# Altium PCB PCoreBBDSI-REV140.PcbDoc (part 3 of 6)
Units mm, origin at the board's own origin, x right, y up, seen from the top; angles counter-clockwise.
Board outline 100 x 72 mm, 6 copper layers (Top Layer, Int1 (GND), Int2 (Sign), Int3 (Sign), Int4 (GND), Bottom Layer), stack 1.551 mm thick; 358 components, 403 nets, 1535 pads, 844 vias.
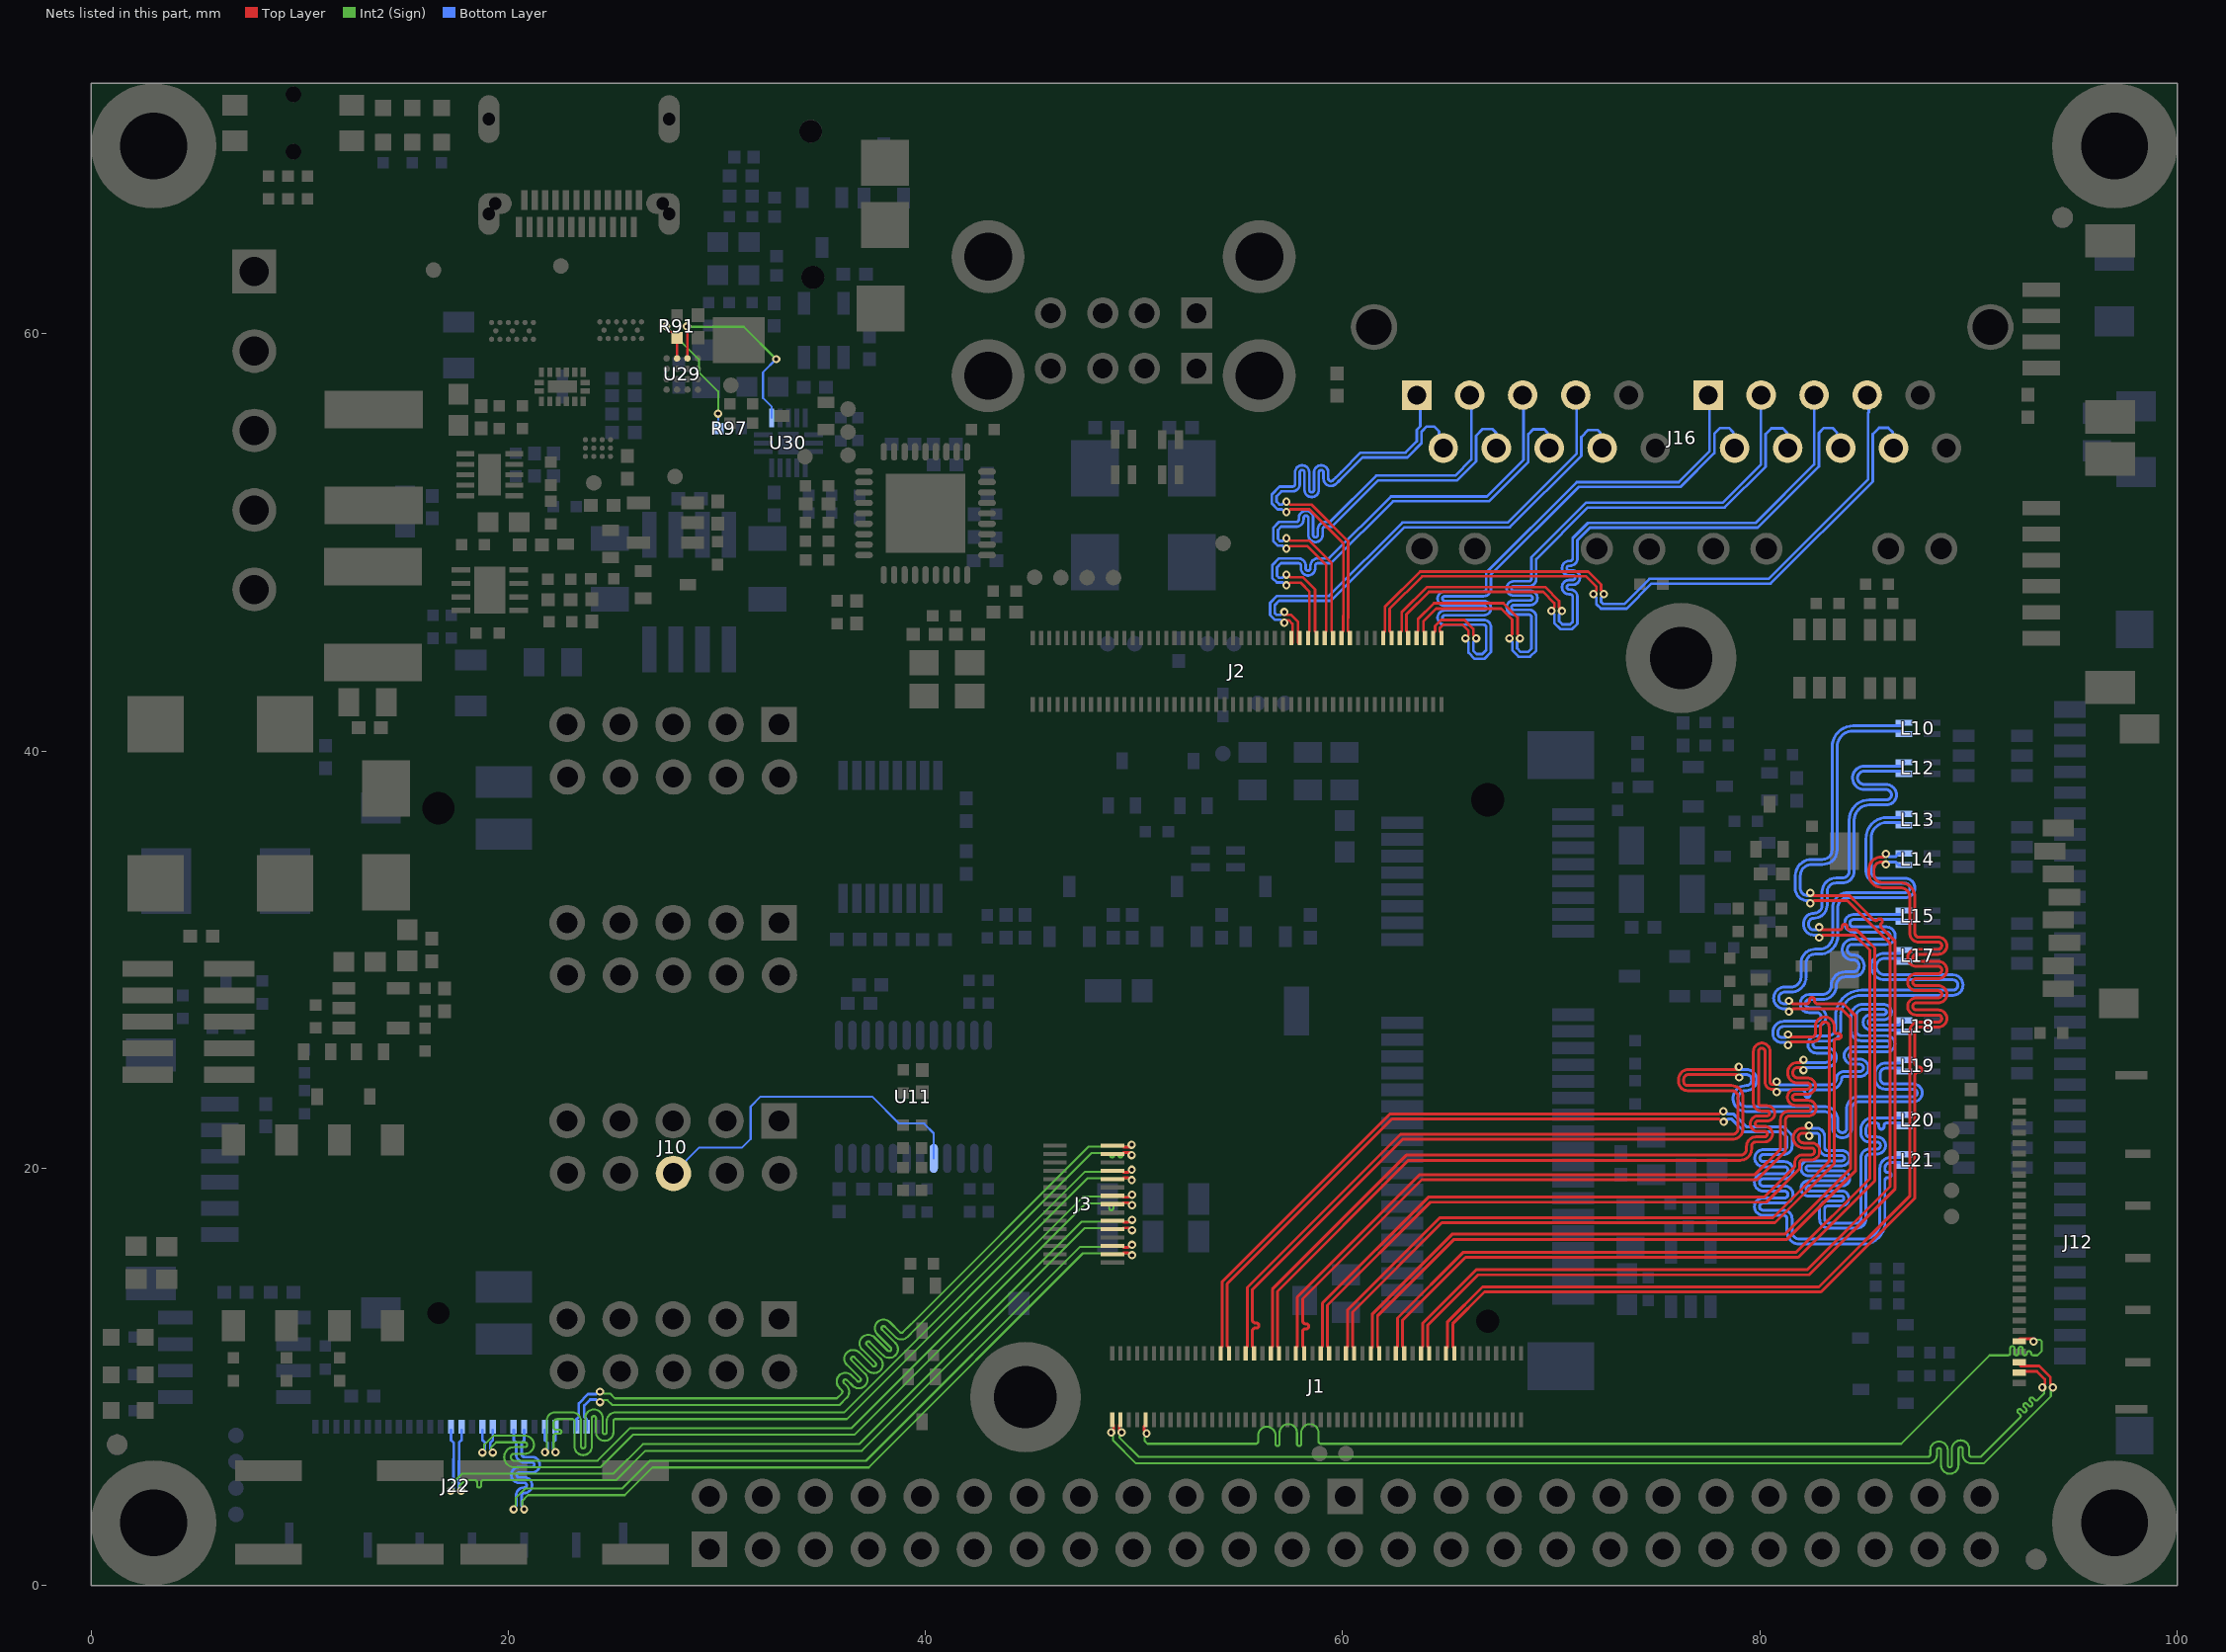
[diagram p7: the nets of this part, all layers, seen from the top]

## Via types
v1: diameter 0.4, hole 0.2, Top Layer to Bottom Layer, tented both sides, 716 vias
v2: diameter 0.5, hole 0.3, Top Layer to Bottom Layer, tented both sides, 102 vias
v3: diameter 0.4, hole 0.2, Top Layer to Bottom Layer, tented bottom, 16 vias
v4: diameter 0.9, hole 0.9, Top Layer to Bottom Layer, 6 vias
v5: diameter 0.5, hole 0.5, Top Layer to Bottom Layer, 2 vias
v6: diameter 3.2, hole 3.2, Top Layer to Bottom Layer, tented both sides, 2 vias

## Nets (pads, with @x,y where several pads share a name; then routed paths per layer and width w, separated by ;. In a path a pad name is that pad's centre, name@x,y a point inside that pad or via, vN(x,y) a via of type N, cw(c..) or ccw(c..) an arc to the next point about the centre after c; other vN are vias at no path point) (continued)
CSI_A_DATA2_P: J1.92 J12.5 | length 53.9
  Top Layer w0.127: J1.92@50.55,7.94 50.55,7.69 50.48,7.62 50.48,7.427 50.6,7.307 v1(50.6,7.29) ; J12.5@92.435,11.7 92.435,11.813 92.446,11.825 93.135,11.825 v1@93.14,11.82 ; v1@93.077,11.688 v1(93.12,11.688)
  Int2 (Sign) w0.1: v1(50.6,7.29) 50.6,7.209 50.51,7.119 50.51,6.918 50.638,6.79 55.844,6.79 ccw(c55.844,6.89) 55.944,6.89 55.944,7.189 cw(c56.361,7.189) 56.778,7.189 56.778,6.783 ccw(c56.878,6.783) 56.978,6.783 56.978,7.316 cw(c57.395,7.316) 57.811,7.316 57.811,6.783 ccw(c57.911,6.783) 58.011,6.783 58.011,7.316 cw(c58.428,7.316) 58.845,7.316 58.845,6.89 ccw(c58.945,6.89) 58.945,6.79 86.772,6.79 91.012,11.03 91.849,11.03 91.899,11.03 ccw(c91.899,11.13) 91.999,11.13 91.999,11.367 cw(c92.099,11.367) 92.199,11.367 92.199,11.13 ccw(c92.299,11.13) 92.399,11.13 92.399,11.341 cw(c92.499,11.341) 92.599,11.341 92.599,11.13 ccw(c92.699,11.13) 92.799,11.13 cw(c92.899,11.13) 92.999,11.13 ccw(c93.099,11.13) 93.099,11.03 93.273,11.03 93.3,11.03 93.513,11.243 93.513,11.687 93.42,11.78 93.293,11.78 93.201,11.688 v1(93.12,11.688)
CSI_A_DATA3_N: J1.100 J12.3 | length 53.9
  Top Layer w0.127: v1(48.9,7.33) 48.923,7.33 49.02,7.427 49.02,7.694 48.986,7.694 48.95,7.73 J1.100@48.95,7.94 ; J12.3@92.435,10.7 92.435,10.614 92.492,10.556 92.492,10.529 92.501,10.52 93.387,10.52 93.919,9.988 93.919,9.667 94.038,9.548 v1(94.038,9.49)
  Int2 (Sign) w0.1: v1(48.9,7.33) 48.9,7.249 48.992,7.157 48.992,6.949 50.09,5.85 88.068,5.85 ccw(c88.068,6.267) 88.485,6.267 88.485,6.482 cw(c88.585,6.482) 88.585,6.582 cw(c88.585,6.482) 88.685,6.482 88.685,5.767 ccw(c89.101,5.767) 89.101,5.35 ccw(c89.101,5.767) 89.518,5.767 89.518,6.538 cw(c89.618,6.538) 89.618,6.638 cw(c89.618,6.538) 89.718,6.538 89.718,6.267 ccw(c90.135,6.267) 90.135,5.85 90.728,5.85 93.947,9.069 93.947,9.35 94.038,9.442 v1(94.038,9.49)
CSI_A_DATA3_P: J1.98 J12.2 | length 53.8
  Top Layer w0.127: J1.98@49.35,7.94 49.35,7.73 49.313,7.694 49.28,7.694 49.28,7.427 49.377,7.33 v1(49.4,7.33) ; J12.2@92.435,10.2 92.495,10.26 93.279,10.26 93.658,9.88 93.658,9.667 93.538,9.548 v1(93.538,9.49)
  Int2 (Sign) w0.1: v1(49.4,7.33) 49.4,7.249 49.308,7.157 49.308,7.08 50.222,6.167 88.068,6.167 ccw(c88.068,6.267) 88.168,6.267 88.168,6.482 cw(c88.585,6.482) 88.585,6.899 cw(c88.585,6.482) 89.001,6.482 89.001,5.767 ccw(c89.101,5.767) 89.101,5.667 ccw(c89.101,5.767) 89.201,5.767 89.201,6.538 cw(c89.618,6.538) 89.618,6.954 cw(c89.618,6.538) 90.035,6.538 90.035,6.267 ccw(c90.135,6.267) 90.135,6.167 90.597,6.167 92.437,8.007 92.469,8.039 92.472,8.042 ccw(c92.402,8.113) 92.472,8.184 92.375,8.281 cw(c92.446,8.352) 92.375,8.423 cw(c92.446,8.352) 92.516,8.423 92.614,8.325 ccw(c92.685,8.396) 92.755,8.325 ccw(c92.685,8.396) 92.755,8.467 92.658,8.564 cw(c92.728,8.635) 92.658,8.706 cw(c92.728,8.635) 92.799,8.706 92.897,8.608 ccw(c92.967,8.679) 93.038,8.608 ccw(c92.967,8.679) 93.038,8.749 92.952,8.836 cw(c93.022,8.907) 92.952,8.977 cw(c93.022,8.907) 93.093,8.977 93.179,8.891 ccw(c93.25,8.962) 93.321,8.891 93.457,9.027 93.63,9.2 93.63,9.35 93.538,9.442 v1(93.538,9.49)
CSI_B_CLK_N: J3.6 J22.9 | length 42.2
  Top Layer w0.127: J3.6@49.174,16.276 49.424,16.276 49.494,16.206 49.72,16.206 49.839,16.326 v1(49.897,16.326)
  Int2 (Sign) w0.1: v1(20.262,3.65) 20.262,3.731 20.353,3.823 20.353,4.185 20.813,4.644 25.456,4.644 26.782,5.97 37.15,5.97 47.414,16.234 49.724,16.234 49.816,16.326 v1(49.897,16.326)
  Bottom Layer w0.127: J22.9@20.26,7.46 20.26,6.96 20.38,6.84 20.38,6.477 20.38,6.283 ccw(c20.768,6.283) 20.768,5.894 21.135,5.894 cw(c21.135,5.782) 21.135,5.669 20.516,5.669 ccw(c20.516,5.294) 20.516,4.919 20.768,4.919 cw(c20.768,4.807) 20.768,4.694 ccw(c20.768,4.305) 20.38,4.305 20.38,4.021 ccw(c20.511,4.021) 20.38,4.007 20.38,3.829 ; v1(20.262,3.65) 20.262,3.708 20.381,3.827
CSI_B_CLK_P: J3.4 J22.8 | length 41.7
  Top Layer w0.127: J3.4@49.174,15.876 49.424,15.876 49.494,15.946 49.72,15.946 49.839,15.826 v1(49.897,15.826)
  Int2 (Sign) w0.1: v1(20.762,3.65) 20.762,3.731 20.67,3.823 20.67,4.053 20.944,4.327 25.587,4.327 26.913,5.653 37.281,5.653 47.546,15.918 49.724,15.918 49.816,15.826 v1(49.897,15.826)
  Bottom Layer w0.127: 20.641,3.937 20.641,4.007 ccw(c20.511,4.021) 20.642,4.021 20.642,4.305 cw(c20.768,4.305) 20.768,4.432 ccw(c20.768,4.807) 20.768,5.181 20.516,5.181 cw(c20.516,5.294) 20.516,5.407 21.135,5.407 ccw(c21.135,5.782) 21.135,6.157 20.768,6.157 cw(c20.768,6.283) 20.642,6.283 20.642,6.477 20.642,6.839 20.64,6.84 20.76,6.96 J22.8@20.76,7.46 ; 20.642,3.937 20.642,3.827 20.762,3.708 v1(20.762,3.65)
CSI_B_DATA0_N: J3.12 J22.15 | length 42.3
  Top Layer w0.127: J3.12@49.174,17.476 49.424,17.476 49.494,17.406 49.723,17.406 49.842,17.526 v1(49.9,17.526)
  Int2 (Sign) w0.1: v1(17.252,4.53) 17.252,4.611 v1@17.343,4.703 ; v1@17.343,4.53 v1@17.343,4.703 ; v1(49.9,17.526) 49.819,17.526 49.727,17.434 47.484,17.434 36.82,6.77 26.452,6.77 25.046,5.364 19.25,5.364 18.255,5.364 17.803,5.364 17.343,4.905 v1@17.343,4.703
  Bottom Layer w0.127: v1@17.252,4.41 17.371,4.53 17.371,4.708 17.375,4.712 17.375,6.069 17.38,6.073 17.38,6.84 17.26,6.96 J22.15@17.26,7.46
CSI_B_DATA0_P: J3.10 J22.14 | length 42.3
  Top Layer w0.127: J3.10@49.174,17.076 49.424,17.076 49.494,17.146 49.723,17.146 49.842,17.026 v1(49.9,17.026)
  Int2 (Sign) w0.1: v1@17.66,4.53 v1@17.66,4.703 ; v1(17.752,4.53) 17.752,4.611 v1@17.66,4.703 ; v1(49.9,17.026) 49.819,17.026 49.727,17.118 47.616,17.118 36.951,6.453 26.583,6.453 25.177,5.047 19.32,5.047 18.803,5.047 ccw(c18.803,4.947) 18.703,4.947 18.703,4.792 cw(c18.603,4.792) 18.503,4.792 18.503,4.947 ccw(c18.403,4.947) 18.403,5.047 18.153,5.047 17.934,5.047 17.66,4.773 v1@17.66,4.703
  Bottom Layer w0.127: v1@17.752,4.488 17.636,4.604 17.636,5.961 17.64,5.965 17.64,6.84 17.76,6.96 J22.14@17.76,7.46
CSI_B_DATA1_N: J3.18 J22.12 | length 41.8
  Top Layer w0.127: J3.18@49.174,18.676 49.424,18.676 49.494,18.606 49.723,18.606 49.842,18.726 v1(49.9,18.726)
  Int2 (Sign) w0.1: v1(18.76,6.37) 18.76,6.451 18.852,6.543 18.852,6.74 19.289,7.177 20.79,7.177 cw(c20.79,6.74) 21.227,6.74 cw(c20.797,6.74) 20.797,6.31 20.28,6.31 ccw(c20.28,6.15) 20.12,6.15 ccw(c20.293,6.15) 20.293,5.977 24.276,5.977 25.839,7.54 36.46,7.54 47.554,18.634 48.458,18.634 49.727,18.634 49.819,18.726 v1(49.9,18.726)
  Bottom Layer w0.127: v1(18.76,6.37) 18.76,6.428 18.88,6.547 18.88,6.84 18.76,6.96 J22.12@18.76,7.46
CSI_B_DATA1_P: J3.16 J22.11 | length 41.8
  Top Layer w0.127: J3.16@49.174,18.276 49.424,18.276 49.494,18.346 49.723,18.346 49.842,18.226 v1(49.9,18.226)
  Int2 (Sign) w0.1: v1(19.26,6.37) 19.26,6.451 19.168,6.543 19.168,6.608 19.42,6.86 20.79,6.86 cw(c20.79,6.74) 20.91,6.74 cw(c20.797,6.74) 20.797,6.627 20.28,6.627 ccw(c20.28,6.15) 19.803,6.15 ccw(c20.293,6.15) 20.293,5.66 24.407,5.66 25.97,7.223 36.591,7.223 47.686,18.318 48.458,18.318 48.708,18.318 cw(c48.708,18.218) 48.808,18.218 48.808,18.081 ccw(c48.908,18.081) 49.008,18.081 49.008,18.218 cw(c49.108,18.218) 49.108,18.318 49.41,18.318 49.727,18.318 49.819,18.226 v1(49.9,18.226)
  Bottom Layer w0.127: v1(19.26,6.37) 19.26,6.428 19.14,6.547 19.14,6.84 19.26,6.96 J22.11@19.26,7.46
CSI_B_DATA2_N: J3.24 J22.6 | length 41.5
  Top Layer w0.127: J3.24@49.174,19.876 49.424,19.876 49.494,19.806 49.713,19.806 49.832,19.926 v1(49.89,19.926)
  Int2 (Sign) w0.1: v1(21.76,6.39) 21.76,6.471 21.852,6.563 21.852,7.922 cw(c22.22,7.922) 22.22,8.29 22.348,8.29 23.073,8.29 cw(c23.073,7.873) 23.49,7.873 23.49,6.663 ccw(c23.59,6.663) 23.59,6.563 ccw(c23.59,6.663) 23.69,6.663 23.69,8.022 cw(c24.107,8.022) 24.107,8.438 cw(c24.107,8.022) 24.524,8.022 24.524,7.348 ccw(c24.624,7.348) 24.624,7.248 ccw(c24.624,7.348) 24.724,7.348 24.724,7.873 cw(c25.14,7.873) 25.14,8.29 26.054,8.29 36.1,8.29 47.644,19.834 49.717,19.834 49.809,19.926 v1(49.89,19.926)
  Bottom Layer w0.127: v1(21.76,6.39) 21.76,6.448 21.88,6.567 21.88,6.84 21.76,6.96 J22.6@21.76,7.46
CSI_B_DATA2_P: J3.22 J22.5 | length 41.6
  Top Layer w0.127: J3.22@49.174,19.476 49.424,19.476 49.494,19.546 49.713,19.546 49.832,19.426 v1(49.89,19.426)
  Int2 (Sign) w0.1: v1(22.26,6.39) 22.26,6.471 22.214,6.517 22.168,6.563 22.168,7.167 cw(c22.268,7.167) 22.268,7.267 22.448,7.267 ccw(c22.448,7.367) 22.448,7.467 22.268,7.467 cw(c22.268,7.567) 22.168,7.567 22.168,7.79 cw(c22.348,7.79) 22.348,7.97 22.351,7.973 23.073,7.973 cw(c23.073,7.873) 23.173,7.873 23.173,6.663 ccw(c23.59,6.663) 23.59,6.247 ccw(c23.59,6.663) 24.007,6.663 24.007,8.022 cw(c24.107,8.022) 24.107,8.122 cw(c24.107,8.022) 24.207,8.022 24.207,7.348 ccw(c24.624,7.348) 24.624,6.932 ccw(c24.624,7.348) 25.04,7.348 25.04,7.873 cw(c25.14,7.873) 25.14,7.973 26.054,7.973 36.231,7.973 47.776,19.518 49.717,19.518 49.809,19.426 v1(49.89,19.426)
  Bottom Layer w0.127: v1(22.26,6.39) 22.26,6.448 22.14,6.567 22.14,6.84 22.26,6.96 J22.5@22.26,7.46
CSI_B_DATA3_N: J3.30 J22.3 | length 42.2
  Top Layer w0.127: J3.30@49.174,21.076 49.424,21.076 49.494,21.006 49.8,21.006 49.887,21.094 v1(49.887,21.126)
  Int2 (Sign) w0.1: v1(24.4,9.288) 24.481,9.288 24.573,9.197 24.881,9.197 25.111,8.967 34.518,8.967 35.749,8.967 35.992,9.21 ; 35.992,9.353 cw(c35.922,9.281) 35.992,9.21 ; 35.992,9.353 35.865,9.48 cw(c36.16,9.774) 35.865,10.069 cw(c36.16,9.774) 36.455,10.069 36.73,9.794 ; 36.73,9.793 ccw(c36.801,9.864) 36.872,9.793 ccw(c36.801,9.864) 36.872,9.934 ; 36.872,9.935 36.232,10.574 cw(c36.527,10.869) 36.232,11.164 cw(c36.527,10.869) 36.822,11.163 37.461,10.524 ccw(c37.532,10.594) 37.603,10.523 ; 37.602,10.666 36.963,11.305 cw(c37.258,11.6) 36.963,11.894 cw(c37.258,11.6) 37.553,11.894 38.192,11.255 ccw(c38.263,11.325) 38.333,11.254 ccw(c38.263,11.325) 38.334,11.396 ; 37.603,10.524 ccw(c37.532,10.594) 37.603,10.665 ; 38.333,11.397 37.694,12.036 cw(c37.989,12.331) 37.694,12.625 cw(c37.989,12.331) 38.284,12.625 38.774,12.135 ccw(c38.845,12.205) 38.916,12.134 39.281,12.499 39.429,12.647 47.816,21.034 49.715,21.034 49.806,21.126 v1(49.887,21.126)
  Bottom Layer w0.127: J22.3@23.26,7.46 23.26,7.96 23.38,8.08 23.38,8.73 23.819,9.169 24.223,9.169 24.342,9.288 v1(24.4,9.288)
CSI_B_DATA3_P: J3.28 J22.2 | length 42.2
  Top Layer w0.127: J3.28@49.174,20.676 49.424,20.676 49.494,20.746 49.8,20.746 49.887,20.658 v1(49.887,20.626)
  Int2 (Sign) w0.1: v1(24.4,8.788) 24.481,8.788 24.573,8.88 24.75,8.88 24.98,8.65 34.835,8.65 35.88,8.65 36.217,8.987 ccw(c35.922,9.281) 36.263,9.521 36.263,9.53 36.09,9.703 cw(c36.16,9.774) 36.089,9.845 cw(c36.16,9.774) 36.231,9.845 ; 36.231,9.844 36.507,9.569 ccw(c36.801,9.864) 37.096,9.569 ccw(c36.801,9.864) 37.096,10.159 36.457,10.798 cw(c36.527,10.869) 36.456,10.939 cw(c36.527,10.869) 36.598,10.94 ; 36.598,10.939 37.238,10.3 ccw(c37.532,10.594) 37.827,10.3 ccw(c37.532,10.594) 37.827,10.889 ; 37.187,11.529 cw(c37.258,11.6) 37.187,11.67 ; 37.187,11.671 cw(c37.258,11.6) 37.328,11.67 37.968,11.031 ccw(c38.263,11.325) 38.558,11.031 ccw(c38.263,11.325) 38.557,11.62 37.918,12.259 cw(c37.989,12.331) 37.918,12.401 ; 37.188,11.528 37.826,10.89 ; 37.918,12.401 cw(c37.989,12.331) 38.059,12.401 ; 38.06,12.401 38.551,11.91 ccw(c38.845,12.205) 39.14,11.91 39.505,12.275 ; 39.505,12.275 39.653,12.423 47.948,20.718 48.501,20.718 48.751,20.718 cw(c48.751,20.618) 48.851,20.618 ccw(c48.951,20.617) 49.051,20.617 cw(c49.151,20.618) 49.251,20.618 ccw(c49.351,20.617) 49.451,20.617 cw(c49.551,20.618) 49.551,20.718 49.715,20.718 49.806,20.626 v1(49.887,20.626)
  Bottom Layer w0.127: J22.2@23.76,7.46 23.76,7.96 23.64,8.08 23.64,8.622 23.927,8.908 24.223,8.908 24.342,8.788 v1(24.4,8.788)
CTS_B_RS232: J10.6 U11.17 | length 16.8
  Bottom Layer w0.1: J10.6@27.92,19.75 29.16,20.99 31.21,20.99 31.62,21.4 31.62,22.95 32.1,23.43 37.447,23.43 38.737,22.14 39.93,22.14 40.395,21.675 U11.17@40.395,20.47
DSI_A_CLK_N: J1.19 L14.4 | length 56.2
  Top Layer w0.141: J1.19@64.948,11.368 64.979,11.399 64.984,11.399 65.029,11.445 65.029,12.64 66.699,14.31 82.831,14.31 87.192,18.672 87.192,24.157 87.192,25.818 ; v1(86.04,35.06) cw(c85.891,35.06) 85.891,34.911 85.8,34.911 ccw(c85.8,34.34) 85.229,34.34 85.229,34.08 ccw(c85.859,34.08) 85.859,33.45 86.72,33.45 cw(c86.72,32.978) 87.192,32.978 87.192,32.673 ; 87.192,25.818 87.192,26.591 cw(c87.604,26.591) 87.604,27.002 88.548,27.002 ccw(c88.548,27.173) 88.718,27.173 ccw(c88.548,27.173) 88.548,27.343 87.493,27.343 cw(c87.493,27.755) 87.082,27.755 cw(c87.493,27.755) 87.493,28.166 88.548,28.166 ccw(c88.548,28.337) 88.718,28.337 ccw(c88.548,28.337) 88.548,28.507 87.493,28.507 cw(c87.493,28.919) 87.082,28.919 cw(c87.493,28.919) 87.493,29.33 88.548,29.33 ccw(c88.548,29.501) 88.718,29.501 ccw(c88.548,29.501) 88.548,29.671 87.493,29.671 cw(c87.493,30.083) 87.082,30.083 cw(c87.493,30.083) 87.493,30.495 88.548,30.495 ccw(c88.548,30.665) 88.718,30.665 ccw(c88.548,30.665) 88.548,30.836 87.604,30.836 cw(c87.604,31.247) 87.192,31.247 87.192,32.673
  Bottom Layer w0.141: v1(86.04,35.06) 86.06,35.06 86.18,34.94 86.52,34.94 86.566,34.986 86.566,35.006 86.645,35.085 L14.4@86.895,35.085
DSI_A_CLK_P: J1.17 L14.1 | length 56.2
  Top Layer w0.141: J1.17@65.348,11.372 65.321,11.399 65.316,11.399 65.271,11.445 65.271,12.541 66.799,14.069 82.931,14.069 87.434,18.572 87.434,24.157 87.434,24.469 cw(c87.575,24.469) 87.575,24.61 87.634,24.61 ccw(c87.634,24.73) 87.754,24.73 ccw(c87.634,24.73) 87.634,24.851 87.575,24.851 cw(c87.575,24.992) 87.434,24.992 87.434,25.491 87.434,25.818 87.434,26.591 cw(c87.604,26.591) 87.604,26.761 88.548,26.761 ccw(c88.548,27.173) 88.959,27.173 ccw(c88.548,27.173) 88.548,27.584 87.493,27.584 cw(c87.493,27.755) 87.323,27.755 cw(c87.493,27.755) 87.493,27.925 88.548,27.925 ccw(c88.548,28.337) 88.959,28.337 ccw(c88.548,28.337) 88.548,28.748 87.493,28.748 cw(c87.493,28.919) 87.323,28.919 cw(c87.493,28.919) 87.493,29.089 88.548,29.089 ccw(c88.548,29.501) 88.959,29.501 ccw(c88.548,29.501) 88.548,29.913 87.493,29.913 cw(c87.493,30.083) 87.323,30.083 cw(c87.493,30.083) 87.493,30.254 88.548,30.254 ccw(c88.548,30.665) 88.959,30.665 ccw(c88.548,30.665) 88.548,31.077 87.604,31.077 cw(c87.604,31.247) 87.434,31.247 87.434,32.673 87.434,32.978 ccw(c86.72,32.978) 86.72,33.691 85.859,33.691 cw(c85.859,34.08) 85.47,34.08 85.47,34.34 cw(c85.8,34.34) 85.8,34.67 85.93,34.67 cw(c85.93,34.56) v1(86.04,34.56)
  Bottom Layer w0.141: v1(86.04,34.56) 86.06,34.56 86.18,34.68 86.52,34.68 86.566,34.634 86.566,34.614 86.645,34.535 L14.1@86.895,34.535
DSI_A_DATA0_N: J1.25 L10.4 | length 56.5
  Top Layer w0.141: J1.25@63.748,10.839 63.748,11.368 63.779,11.399 63.784,11.399 63.829,11.445 63.829,11.914 63.833,11.918 63.833,12.574 66.389,15.13 82.26,15.13 86.242,19.113 86.242,30.773 85.868,31.148 84.186,32.829 82.585,32.829 82.455,32.7 v1(82.41,32.7)
  Bottom Layer w0.141: v1(82.41,32.7) ccw(c82.281,32.7) 82.281,32.829 cw(c82.281,33.415) 81.695,33.415 81.695,34.014 cw(c82.481,34.014) 82.481,34.801 83.001,34.801 ccw(c83.001,35.26) 83.46,35.26 83.46,40.188 cw(c84.474,40.188) 84.474,41.201 86.741,41.201 ccw(c86.741,41.355) L10.4@86.895,41.355
DSI_A_DATA0_P: J1.23 L10.1 | length 55.9
  Top Layer w0.141: J1.23@64.148,11.372 64.121,11.399 64.116,11.399 64.071,11.445 64.071,11.814 64.074,11.818 64.074,12.474 66.489,14.889 82.36,14.889 86.484,19.013 86.484,30.873 86.038,31.318 85.818,31.539 cw(c85.918,31.638) 85.818,31.738 85.837,31.757 ccw(c85.752,31.842) 85.837,31.927 ccw(c85.752,31.842) 85.667,31.927 85.648,31.909 cw(c85.548,32.008) 85.448,31.909 84.746,32.611 84.286,33.071 82.563,33.071 82.554,33.08 v1@82.41,33.08
  Bottom Layer w0.141: v1(82.41,33.2) cw(c82.281,33.2) 82.281,33.071 cw(c82.281,33.415) 81.936,33.415 81.936,34.014 cw(c82.481,34.014) 82.481,34.56 83.001,34.56 ccw(c83.001,35.26) 83.701,35.26 83.701,40.188 cw(c84.474,40.188) 84.474,40.96 86.74,40.96 cw(c86.74,40.805) L10.1@86.895,40.805
DSI_A_DATA1_N: J1.31 L12.4 | length 56.6
  Top Layer w0.141: J1.31@62.548,10.839 62.548,11.368 62.579,11.399 62.584,11.399 62.629,11.445 62.629,12.811 65.791,15.972 81.742,15.972 85.262,19.493 85.262,30.453 84.536,31.18 83.015,31.18 82.885,31.05 v1(82.84,31.05)
  Bottom Layer w0.141: v1(82.84,31.05) ccw(c82.71,31.05) 82.71,31.18 82.58,31.18 cw(c82.58,31.661) 82.099,31.661 82.099,31.74 cw(c82.58,31.74) 82.58,32.221 82.59,32.221 ccw(c82.59,32.611) 82.98,32.611 82.98,33.243 cw(c83.649,33.243) 83.649,33.912 83.951,33.912 ccw(c83.951,34.241) 84.28,34.241 84.28,36.691 cw(c85.245,36.691) 85.245,37.656 86.063,37.656 ccw(c86.063,37.896) 86.303,37.896 ccw(c86.049,37.896) 86.049,38.15 85.001,38.15 cw(c85.001,38.711) 85.011,39.271 86.711,39.271 ccw(c86.711,39.455) L12.4@86.895,39.455
DSI_A_DATA1_P: J1.29 L12.1 | length 56.6
  Top Layer w0.141: J1.29@62.948,10.839 62.948,11.372 62.921,11.399 62.916,11.399 62.871,11.445 62.871,12.711 65.89,15.731 81.842,15.731 85.504,19.393 85.504,30.553 84.636,31.421 84.324,31.421 cw(c84.324,31.562) 84.183,31.562 84.183,31.574 ccw(c84.063,31.574) 84.063,31.694 ccw(c84.063,31.574) 83.942,31.574 83.942,31.562 cw(c83.801,31.562) 83.801,31.421 82.85,31.421 v1@82.72,31.55
  Bottom Layer w0.141: v1(82.84,31.55) cw(c82.71,31.55) 82.71,31.421 82.58,31.421 cw(c82.58,31.661) 82.34,31.661 82.34,31.74 cw(c82.58,31.74) 82.58,31.98 82.59,31.98 ccw(c82.59,32.611) 83.221,32.611 83.221,33.243 cw(c83.649,33.243) 83.649,33.671 83.951,33.671 ccw(c83.951,34.241) 84.521,34.241 84.521,36.691 cw(c85.245,36.691) 85.245,37.415 86.063,37.415 ccw(c86.063,37.896) 86.544,37.896 ccw(c86.049,37.896) 86.049,38.391 85,38.391 cw(c85.001,38.711) 84.994,39.03 85.01,39.03 ccw(c85.011,39.271) 85.013,39.03 86.77,39.03 cw(c86.77,38.905) L12.1@86.895,38.905
DSI_A_DATA2_N: J1.37 L13.4 | length 56
  Top Layer w0.141: J1.37@61.348,11.368 61.379,11.399 61.384,11.399 61.429,11.445 61.429,13.02 65.24,16.831 81.2,16.831 84.349,19.98 84.349,27.201 83.91,27.64 81.565,27.64 81.425,27.5 v1(81.39,27.5)
  Bottom Layer w0.141: v1(81.39,27.5) ccw(c81.251,27.5) 81.251,27.64 81.169,27.64 cw(c81.169,28.15) 80.659,28.15 cw(c81.19,28.15) 81.19,28.681 81.491,28.681 ccw(c81.491,29.16) 81.97,29.16 81.97,29.83 cw(c82.641,29.83) 82.641,30.501 82.862,30.501 ccw(c82.862,31.129) 83.49,31.129 83.49,32.472 cw(c84.226,32.472) 84.226,33.209 86.968,33.209 ccw(c86.968,33.429) 87.188,33.429 ccw(c86.958,33.429) 86.958,33.659 85.686,33.659 cw(c85.686,34.258) 85.684,33.659 85.672,33.659 cw(c85.674,34.246) 85.092,34.169 cw(c85.331,34.199) 85.09,34.188 ccw(c85.013,34.184) 85.09,34.193 cw(c85.686,34.258) 85.09,34.324 85.09,35.821 cw(c86.08,35.821) 86.08,36.811 86.721,36.811 ccw(c86.721,36.985) L13.4@86.895,36.985
DSI_A_DATA2_P: J1.35 L13.1 | length 56
  Top Layer w0.141: J1.35@61.748,11.372 61.721,11.399 61.716,11.399 61.671,11.445 61.671,12.921 65.34,16.59 81.3,16.59 84.59,19.88 84.59,27.301 84.01,27.881 83.072,27.881 82.76,27.881 cw(c82.76,28.022) 82.619,28.022 82.619,28.066 ccw(c82.499,28.066) 82.499,28.186 ccw(c82.499,28.066) 82.378,28.066 82.378,28.022 cw(c82.237,28.022) 82.237,27.881 82.01,27.881 81.565,27.881 81.425,28.02 v1(81.39,28.02)
  Bottom Layer w0.141: v1(81.39,28.02) cw(c81.251,28.02) 81.251,27.881 81.168,27.881 cw(c81.169,28.15) 80.9,28.143 80.9,28.15 cw(c81.19,28.15) 81.19,28.44 81.491,28.44 ccw(c81.491,29.16) 82.211,29.16 82.211,29.83 cw(c82.641,29.83) 82.641,30.26 82.862,30.26 ccw(c82.862,31.129) 83.731,31.129 83.731,32.472 cw(c84.226,32.472) 84.226,32.968 86.968,32.968 ccw(c86.968,33.429) 87.429,33.429 ccw(c86.958,33.429) 86.958,33.9 85.671,33.9 cw(c85.674,34.246) 85.331,34.199 85.331,35.821 cw(c86.08,35.821) 86.08,36.57 86.76,36.57 cw(c86.76,36.435) L13.1@86.895,36.435
DSI_A_DATA3_N: J1.43 L15.4 | length 56.5
  Top Layer w0.141: J1.43@60.148,10.839 60.148,11.368 60.179,11.399 60.184,11.399 60.229,11.445 60.229,13.2 64.653,17.623 80.623,17.623 82.26,19.26 83.32,20.32 83.32,25.731 cw(c83.56,25.753) 83.319,25.753 83.319,26.065 cw(c83.701,26.065) 83.32,26.093 83.32,26.56 cw(c83.701,26.588) 83.319,26.588 83.319,26.735 ; v1(81.35,25.9) cw(c81.5,25.9) 81.5,26.05 82.491,26.05 ccw(c82.491,26.46) 82.729,26.126 ccw(c82.491,26.46) 82.901,26.46 82.901,26.801 cw(c83.111,26.799) 83.314,26.848 ccw(c83.553,26.814) 83.316,26.773 cw(c83.11,26.735) 83.319,26.74 83.319,26.736
  Bottom Layer w0.141: v1(81.35,25.9) ccw(c81.216,25.9) 81.216,26.034 81.02,26.034 cw(c81.02,26.436) 80.619,26.436 80.619,26.51 cw(c81.15,26.51) 81.15,27.041 82.707,27.041 ccw(c82.707,27.262) 82.929,27.262 ccw(c82.732,27.262) 82.732,27.459 82.351,27.459 cw(c82.351,27.871) 81.939,27.871 81.939,27.9 cw(c82.36,27.9) 82.36,28.321 82.99,28.321 ccw(c82.99,28.751) 83.42,28.751 cw(c84.079,28.751) 84.079,29.41 84.47,29.41 ccw(c84.47,29.699) 84.759,29.699 ccw(c84.47,29.699) 84.47,29.989 84.374,29.989 cw(c84.372,30.23) 84.31,29.997 cw(c84.442,30.475) 84.479,30.97 86.059,30.97 ccw(c86.071,31.145) 86.069,31.32 84.49,31.32 cw(c84.49,31.741) 84.454,32.161 86.701,32.161 ccw(c86.701,32.355) L15.4@86.895,32.355
DSI_A_DATA3_P: J1.41 L15.1 | length 56
  Top Layer w0.141: J1.41@60.548,11.372 60.521,11.399 60.516,11.399 60.471,11.445 60.471,13.1 64.753,17.382 80.723,17.382 83.56,20.219 83.56,20.298 ccw(c83.32,20.32) 83.561,20.32 83.561,25.731 ccw(c83.32,25.731) 83.56,25.753 83.56,26.065 cw(c83.701,26.065) 83.701,26.206 83.775,26.206 ccw(c83.775,26.326) 83.895,26.326 ccw(c83.775,26.326) 83.775,26.447 83.701,26.447 cw(c83.701,26.588) 83.56,26.588 83.56,26.736 83.56,26.738 83.56,26.744 ccw(c83.11,26.735) 83.553,26.814 ccw(c83.314,26.848) 83.549,26.903 ccw(c83.111,26.799) 82.66,26.801 ccw(c82.901,26.801) 82.66,26.8 82.66,26.738 ccw(c83.11,26.735) 82.66,26.737 ccw(c82.901,26.737) 82.66,26.736 82.66,26.463 82.66,26.46 cw(c82.491,26.46) 82.491,26.291 81.469,26.291 cw(c81.469,26.41) v1(81.35,26.41)
  Bottom Layer w0.141: v1(81.35,26.41) cw(c81.216,26.41) 81.216,26.276 81.02,26.276 cw(c81.02,26.436) 80.86,26.436 80.86,26.51 cw(c81.15,26.51) 81.15,26.8 82.707,26.8 ccw(c82.707,27.262) 83.17,27.262 ccw(c82.732,27.262) 82.732,27.7 82.351,27.7 cw(c82.351,27.871) 82.18,27.871 82.18,27.9 cw(c82.36,27.9) 82.36,28.08 82.99,28.08 ccw(c82.99,28.751) 83.661,28.751 cw(c84.079,28.751) 84.079,29.169 84.47,29.169 ccw(c84.47,29.699) 85.001,29.699 ccw(c84.47,29.699) 84.47,30.23 84.372,30.23 cw(c84.442,30.475) 84.468,30.729 86.01,30.729 ccw(c86.022,31.144) 86.034,30.729 86.053,30.729 ccw(c86.071,31.145) 86.069,31.561 84.49,31.561 ; 84.489,31.561 cw(c84.49,31.741) 84.467,31.92 86.78,31.92 cw(c86.78,31.805) L15.1@86.895,31.805
DSI_B_CLK_N: J1.49 L20.4 | length 56.6
  Top Layer w0.141: J1.49@58.948,10.839 58.948,11.368 58.979,11.399 58.984,11.399 59.029,11.445 59.029,13.536 64.104,18.611 80.204,18.611 81.669,20.076 81.669,20.259 cw(c82.05,20.259) 82.05,20.64 82.46,20.64 ccw(c82.46,20.8) 82.62,20.8 82.62,20.82 ccw(c82.471,20.82) 82.471,20.969 82.1,20.969 cw(c82.1,21.47) 81.599,21.47 cw(c82.049,21.47) 82.049,21.92 82.22,21.92 ccw(c82.22,22.05) v1(82.35,22.05)
  Bottom Layer w0.141: v1(82.35,22.05) ccw(c82.479,22.05) 82.479,21.921 82.699,21.921 cw(c82.699,21.519) 83.101,21.519 83.101,21.172 83.101,20.981 ccw(c83.242,20.981) 83.242,20.84 83.943,20.84 cw(c83.943,20.479) 83.943,20.117 82.329,20.117 ccw(c82.329,19.996) 82.329,19.876 83.943,19.876 cw(c83.943,19.514) 83.943,19.153 82.329,19.153 ccw(c82.329,19.032) 82.329,18.912 83.905,18.912 cw(c83.905,18.55) 83.905,18.189 83.242,18.189 ccw(c83.242,18.048) 83.101,18.048 83.101,17.582 83.101,17.572 ccw(c83.312,17.572) 83.312,17.361 84.632,17.361 ccw(c84.632,17.568) 84.839,17.568 84.839,20.505 cw(c85.251,20.505) 85.251,20.916 85.609,20.916 ccw(c85.609,21.087) 85.779,21.087 ccw(c85.609,21.087) 85.609,21.257 85.251,21.257 cw(c85.251,21.669) 84.839,21.669 84.839,21.86 cw(c85.389,21.86) 85.389,22.411 86.741,22.411 ccw(c86.741,22.565) L20.4@86.895,22.565
DSI_B_CLK_P: J1.47 L20.1 | length 56.1
  Top Layer w0.141: J1.47@59.348,11.372 59.321,11.399 59.316,11.399 59.271,11.445 59.271,13.436 64.204,18.37 80.304,18.37 81.91,19.976 81.91,20.26 cw(c82.05,20.259) 82.05,20.399 82.46,20.399 ccw(c82.46,20.8) 82.861,20.8 82.861,20.82 ccw(c82.471,20.82) 82.471,21.21 82.1,21.21 cw(c82.1,21.47) 81.84,21.47 cw(c82.049,21.47) 82.049,21.679 82.22,21.679 ccw(c82.22,22.05) 82.237,21.679 cw(c82.231,21.55) v1(82.36,21.55)
  Bottom Layer w0.141: v1(82.36,21.55) cw(c82.489,21.55) 82.489,21.679 82.699,21.679 cw(c82.699,21.519) 82.86,21.52 82.86,21.172 82.86,20.981 ccw(c83.242,20.981) 83.242,20.599 83.943,20.599 cw(c83.943,20.479) 83.943,20.358 82.329,20.358 ccw(c82.329,19.996) 82.329,19.635 83.943,19.635 cw(c83.943,19.514) 83.943,19.394 82.329,19.394 ccw(c82.329,19.032) 82.329,18.671 83.905,18.671 cw(c83.905,18.55) 83.905,18.43 83.242,18.43 ccw(c83.242,18.048) 82.86,18.048 82.86,17.672 82.86,17.582 82.86,17.572 ccw(c83.312,17.572) 83.312,17.12 84.632,17.12 ccw(c84.632,17.568) 85.08,17.568 85.08,18.37 85.08,20.505 cw(c85.251,20.505) 85.251,20.675 85.609,20.675 ccw(c85.609,21.087) 86.02,21.087 ccw(c85.609,21.087) 85.609,21.498 85.251,21.498 cw(c85.251,21.669) 85.08,21.669 85.08,21.86 cw(c85.389,21.86) 85.253,22.138 cw(c85.389,21.86) 85.323,22.162 85.389,22.169 85.564,22.169 cw(c85.564,22.028) 85.705,22.028 85.705,21.987 ccw(c85.826,21.987) 85.826,21.866 ccw(c85.826,21.987) 85.946,21.987 85.946,22.028 cw(c86.087,22.028) 86.087,22.169 86.741,22.169 86.824,22.145 cw(c86.741,22.015) L20.1@86.895,22.015
DSI_B_DATA0_N: J1.55 L17.4 | length 55.9
  Top Layer w0.141: J1.55@57.748,11.368 57.759,11.379 57.779,11.399 57.779,11.405 57.82,11.445 57.82,13.435 57.82,13.814 57.839,13.834 57.839,13.84 63.689,19.69 79.76,19.69 80.989,20.919 80.989,22.33 cw(c81.399,22.33) 81.399,22.74 82.32,22.74 ccw(c82.32,22.87) 82.45,22.87 ccw(c82.311,22.87) 82.311,23.009 81.708,23.009 cw(c81.708,23.399) 81.71,23.79 82.268,23.79 ccw(c82.268,23.941) 82.419,23.941 ccw(c82.271,23.941) 82.271,24.089 81.8,24.089 cw(c81.8,24.55) 81.339,24.55 81.339,24.6 cw(c81.81,24.6) 81.81,25.071 81.96,25.071 ccw(c81.96,25.2) v1(82.09,25.2)
  Bottom Layer w0.141: v1(82.09,25.2) ccw(c82.22,25.2) 82.22,25.071 83.171,25.071 ccw(c83.171,25.32) 83.42,25.32 ccw(c83.22,25.32) 83.22,25.52 82.709,25.52 cw(c82.709,25.93) 82.299,25.93 cw(c82.7,25.93) 82.7,26.331 83.234,26.331 ccw(c83.234,26.727) 83.63,26.727 83.629,26.75 83.629,27.29 cw(c84.869,27.29) 84.869,28.53 89.259,28.53 ccw(c89.245,28.779) 89.487,28.842 ccw(c89.245,28.779) 89.243,29.029 85.981,29.029 cw(c85.981,29.67) 85.34,29.67 cw(c85.971,29.67) 85.971,30.301 86.741,30.301 ccw(c86.741,30.455) L17.4@86.895,30.455
DSI_B_DATA0_P: J1.53 L17.1 | length 55.9
  Top Layer w0.141: J1.53@58.148,11.372 58.121,11.399 58.121,11.405 58.08,11.445 58.08,11.848 58.08,12.159 cw(c58.221,12.159) 58.221,12.3 58.251,12.3 ccw(c58.251,12.421) 58.371,12.421 ccw(c58.251,12.421) 58.251,12.541 58.221,12.541 cw(c58.221,12.682) 58.08,12.682 58.08,13.327 58.08,13.74 63.789,19.449 79.86,19.449 81.23,20.819 81.23,22.33 cw(c81.399,22.33) 81.399,22.499 82.32,22.499 ccw(c82.32,22.87) 82.691,22.87 ccw(c82.311,22.87) 82.311,23.25 81.707,23.25 cw(c81.708,23.399) 81.707,23.549 81.709,23.549 ccw(c81.71,23.79) 81.711,23.549 82.268,23.549 ccw(c82.268,23.941) 82.66,23.941 ccw(c82.271,23.941) 82.271,24.33 81.8,24.33 cw(c81.8,24.55) 81.58,24.55 81.58,24.6 cw(c81.81,24.6) 81.81,24.83 81.96,24.83 cw(c81.96,24.7) v1(82.09,24.7)
  Bottom Layer w0.141: v1(82.09,24.7) cw(c82.22,24.7) 82.22,24.83 83.171,24.83 ccw(c83.171,25.32) 83.661,25.32 ccw(c83.22,25.32) 83.22,25.761 82.709,25.761 cw(c82.709,25.93) 82.54,25.93 cw(c82.7,25.93) 82.7,26.09 83.24,26.09 ccw(c83.24,26.65) 83.301,26.093 ; 83.301,26.09 ccw(c83.301,26.659) 83.87,26.659 83.87,26.69 ccw(c83.234,26.727) 83.871,26.727 ccw(c83.63,26.727) 83.871,26.737 83.87,26.755 83.87,27.29 cw(c84.869,27.29) 84.869,28.289 89.264,28.289 ccw(c89.245,28.779) 89.246,29.27 85.981,29.27 cw(c85.981,29.67) 85.581,29.67 cw(c85.971,29.67) 85.971,30.059 86.741,30.059 cw(c86.741,29.905) L17.1@86.895,29.905
DSI_B_DATA1_N: J1.61 L18.4 | length 56.1
  Top Layer w0.141: J1.61@56.548,11.368 56.579,11.399 56.584,11.399 56.629,11.445 56.629,14.2 63.049,20.62 79.059,20.62 ccw(c79.059,20.92) 79.359,20.92 79.359,21.049 cw(c79.81,21.049) 79.81,21.5 80.22,21.5 ccw(c80.22,21.64) 80.36,21.64 ccw(c80.24,21.64) 80.24,21.76 79.909,21.76 cw(c79.909,22.13) 79.539,22.13 cw(c79.92,22.13) 79.92,22.511 80.351,22.511 ccw(c80.351,22.63) 80.47,22.63 ccw(c80.35,22.63) 80.35,22.75 80.06,22.75 cw(c80.06,23.121) 79.689,23.121 79.689,25.318 ; 79.689,25.319 cw(c80.09,25.319) 79.689,25.32 79.689,25.596 cw(c80.09,25.597) 80.491,25.585 80.491,24.119 ccw(c80.59,24.119) 80.59,24.021 80.671,24.021 ccw(c80.671,24.15) v1(80.8,24.15)
  Bottom Layer w0.141: v1(80.8,24.15) ccw(c80.95,24.15) 80.95,24 83.34,24 ccw(c83.34,24.341) 83.681,24.34 cw(c83.922,24.341) 83.752,24.512 cw(c84.042,24.222) 84.042,24.632 84.792,24.632 ccw(c84.792,24.804) 84.964,24.804 ccw(c84.79,24.804) 84.79,24.979 84.451,24.979 cw(c84.458,25.399) 84.458,25.82 86.089,25.82 ccw(c86.089,25.955) 86.224,25.955 ccw(c86.07,25.955) 86.07,26.109 84.845,26.109 cw(c84.845,26.575) 84.379,26.575 84.379,27.309 cw(c84.921,27.309) 84.921,27.851 85.833,27.851 cw(c85.85,27.485) 85.866,27.851 85.924,27.851 cw(c85.94,27.485) 85.94,27.119 cw(c85.94,27.36) 85.938,27.119 85.852,27.119 cw(c85.85,27.485) 85.849,27.119 ; 85.31,27.119 ccw(c85.31,26.989) 85.308,27.119 ccw(c85.31,26.994) 85.304,26.87 86.68,26.87 ccw(c86.68,26.931) 86.741,26.931 ccw(c86.741,27.085) L18.4@86.895,27.085 ; 85.311,27.119 85.848,27.119
DSI_B_DATA1_P: J1.59 L18.1 | length 56.1
  Top Layer w0.141: J1.59@56.948,11.372 56.921,11.399 56.916,11.399 56.871,11.445 56.871,14.101 63.149,20.379 79.059,20.379 ccw(c79.059,20.92) 79.6,20.92 79.6,21.049 cw(c79.81,21.049) 79.81,21.259 80.22,21.259 ccw(c80.22,21.64) 80.601,21.64 ccw(c80.24,21.64) 80.24,22.001 79.909,22.001 cw(c79.909,22.13) 79.78,22.13 cw(c79.92,22.13) 79.92,22.27 80.351,22.27 ccw(c80.351,22.63) 80.711,22.63 ccw(c80.35,22.63) 80.35,22.991 80.06,22.991 cw(c80.06,23.121) 79.93,23.121 79.93,25.591 cw(c80.09,25.591) 80.25,25.594 cw(c80.09,25.597) 80.25,25.591 ccw(c80.491,25.585) 80.25,25.584 ; 80.25,25.583 80.25,25.581 ccw(c80.491,25.579) 80.25,25.578 80.25,24.119 ccw(c80.59,24.119) 80.59,23.779 80.671,23.779 cw(c80.671,23.65) v1(80.8,23.65)
  Bottom Layer w0.141: v1(80.8,23.65) cw(c81.08,23.65) 80.831,23.778 ccw(c80.95,24.15) 80.95,23.759 81.19,23.759 82.016,23.759 cw(c82.016,23.618) 82.157,23.618 82.157,23.51 ccw(c82.278,23.51) 82.278,23.389 ccw(c82.278,23.51) 82.398,23.51 82.398,23.618 cw(c82.539,23.618) 82.539,23.759 82.61,23.759 83.34,23.759 ccw(c83.34,24.341) 83.921,24.307 cw(c83.999,24.303) 83.963,24.371 cw(c84.042,24.222) 84.042,24.391 84.792,24.391 ccw(c84.792,24.804) 85.206,24.804 ccw(c84.79,24.804) 84.79,25.22 84.455,25.22 cw(c84.458,25.399) 84.458,25.579 86.089,25.579 ccw(c86.089,25.955) 86.465,25.955 ccw(c86.07,25.955) 86.07,26.35 84.845,26.35 cw(c84.845,26.575) 84.62,26.575 84.62,27.309 cw(c84.921,27.309) 84.921,27.61 85.93,27.61 cw(c85.94,27.485) 85.94,27.36 85.31,27.36 ccw(c85.31,26.994) 85.3,26.629 86.766,26.629 L18.1@86.895,26.535
DSI_B_DATA2_N: J1.67 L19.4 | length 56
  Top Layer w0.141: J1.67@55.348,11.368 55.379,11.399 55.384,11.399 55.429,11.445 55.429,14.279 62.77,21.62 78.669,21.62 ccw(c78.669,21.901) 78.95,21.901 78.95,23.416 ccw(c78.648,23.416) 78.648,23.719 76.53,23.719 cw(c76.53,24.14) 76.109,24.14 76.109,24.27 cw(c76.565,24.27) 76.565,24.725 77.123,24.725 78.855,24.725 ccw(c78.855,24.86) v1(78.99,24.86)
  Bottom Layer w0.141: v1(78.99,24.86) ccw(c79.125,24.86) 79.125,24.725 79.366,24.725 cw(c79.366,24.251) 79.84,24.251 79.84,24.21 cw(c79.348,24.21) 79.35,23.718 cw(c79.348,23.959) 79.341,23.718 ccw(c79.328,23.34) 79.326,22.961 83.08,22.961 cw(c83.08,22.311) 83.333,22.91 cw(c83.08,22.311) 83.73,22.311 83.73,21.92 ccw(c83.95,21.92) 83.95,21.7 ccw(c83.95,21.909) 84.159,21.909 84.159,22.85 cw(c84.74,22.85) 84.165,22.936 cw(c84.74,22.85) 84.74,23.431 87.363,23.431 ccw(c87.361,23.611) 87.359,23.79 86.01,23.79 cw(c86.01,24.27) 85.53,24.27 85.53,24.539 cw(c86.022,24.539) 86.022,25.031 86.741,25.031 ccw(c86.741,25.185) L19.4@86.895,25.185
DSI_B_DATA2_P: J1.65 L19.1 | length 56
  Top Layer w0.141: J1.65@55.748,11.372 55.721,11.399 55.716,11.399 55.71,11.405 55.671,11.445 55.671,12.199 cw(c55.812,12.199) 55.812,12.34 55.861,12.34 ccw(c55.861,12.461) 55.982,12.461 ccw(c55.861,12.461) 55.861,12.581 55.812,12.581 cw(c55.812,12.722) 55.671,12.722 55.671,13.025 55.671,14.18 62.87,21.379 78.669,21.379 ccw(c78.669,21.901) 79.191,21.901 79.191,23.416 ccw(c78.648,23.416) 78.648,23.96 76.53,23.96 cw(c76.53,24.14) 76.35,24.14 76.35,24.27 cw(c76.565,24.27) 76.565,24.484 78.866,24.484 cw(c78.866,24.35) v1(79,24.35)
  Bottom Layer w0.141: v1(79,24.35) cw(c79.135,24.35) 79.135,24.484 79.366,24.484 cw(c79.366,24.251) 79.599,24.251 79.599,24.21 cw(c79.348,24.21) 79.348,23.959 ccw(c79.328,23.34) 79.326,22.72 83.08,22.72 cw(c83.08,22.311) 83.489,22.311 83.489,21.92 ccw(c83.95,21.92) 83.95,21.459 ccw(c83.95,21.909) 84.4,21.909 84.4,22.85 cw(c84.74,22.85) 84.74,23.19 87.187,23.19 ccw(c87.19,23.61) 87.194,23.19 87.363,23.19 ccw(c87.363,23.431) 87.371,23.19 ccw(c87.361,23.611) 87.358,24.031 86.01,24.031 cw(c86.01,24.27) 85.771,24.27 85.771,24.539 cw(c86.022,24.539) 86.022,24.79 86.74,24.79 cw(c86.74,24.635) L19.1@86.895,24.635
DSI_B_DATA3_N: J1.73 L21.4 | length 56
  Top Layer w0.141: J1.73@54.148,11.368 54.179,11.399 54.179,11.405 54.219,11.444 54.219,14.56 62.26,22.601 78.051,22.601 78.18,22.73 v1(78.25,22.73)
  Bottom Layer w0.141: v1(78.25,22.73) 78.32,22.73 78.46,22.59 78.75,22.59 79.35,21.99 81.13,21.99 81.405,21.715 81.541,21.579 81.541,21.065 cw(c81.129,21.065) 81.129,20.653 80.168,20.653 ccw(c80.168,20.483) 79.997,20.483 ccw(c80.168,20.483) 80.168,20.312 81.176,20.312 cw(c81.176,19.901) 81.587,19.901 cw(c81.176,19.901) 81.176,19.489 80.15,19.489 ccw(c80.15,19.319) 79.979,19.319 ccw(c80.15,19.319) 80.15,19.148 81.176,19.148 cw(c81.176,18.737) 81.587,18.737 cw(c81.176,18.737) 81.176,18.325 80.15,18.325 ccw(c80.15,18.155) 79.979,18.155 ccw(c80.15,18.155) 80.15,17.984 81.129,17.984 cw(c81.129,17.573) 81.541,17.573 81.541,17.382 81.541,16.96 ccw(c81.901,16.96) 81.901,16.6 85.076,16.6 ccw(c84.901,17.448) 85.749,17.273 85.749,20 cw(c86.259,20) 86.259,20.511 86.741,20.511 L21.4@86.895,20.665
DSI_B_DATA3_P: J1.71 L21.1 | length 56
  Top Layer w0.141: J1.71@54.548,11.372 54.521,11.399 54.521,11.405 54.46,11.465 54.46,14.46 62.36,22.36 78.046,22.36 78.137,22.27 78.21,22.27 v1(78.26,22.22)
  Bottom Layer w0.141: v1(78.26,22.22) 78.31,22.27 78.383,22.27 78.463,22.349 78.65,22.349 79.25,21.749 81.03,21.749 81.064,21.715 81.3,21.479 81.3,21.065 cw(c81.129,21.065) 81.129,20.894 80.168,20.894 ccw(c80.168,20.483) 79.756,20.483 ccw(c80.168,20.483) 80.168,20.071 81.176,20.071 cw(c81.176,19.901) 81.346,19.901 cw(c81.176,19.901) 81.176,19.73 80.15,19.73 ccw(c80.15,19.319) 79.738,19.319 ccw(c80.15,19.319) 80.15,18.907 81.176,18.907 cw(c81.176,18.737) 81.346,18.737 cw(c81.176,18.737) 81.176,18.566 80.15,18.566 ccw(c80.15,18.155) 79.738,18.155 ccw(c80.15,18.155) 80.15,17.743 81.129,17.743 cw(c81.129,17.573) 81.3,17.573 81.3,17.382 81.3,16.95 ccw(c81.891,16.95) 81.891,16.359 85.099,16.359 ccw(c84.901,17.448) 85.99,17.25 85.99,17.472 85.99,19.41 cw(c86.131,19.41) 86.131,19.551 86.171,19.551 ccw(c86.171,19.672) 86.291,19.672 ccw(c86.171,19.672) 86.171,19.792 86.131,19.792 cw(c86.131,19.933) 85.99,19.933 85.99,20 cw(c86.259,20) 85.99,20.004 cw(c86.259,20) 86.259,20.269 86.741,20.269 L21.1@86.895,20.115
EN_SRC: R91.2 R97.2 U29.B4 | length 7.9
  Top Layer w0.1: v1(27.56,60.35) 27.56,60.33 R91.2@28.09,59.8 U29.B4@28.09,58.82
  Int2 (Sign) w0.1: v1(27.56,60.35) 29.14,58.77 29.14,58.15 30.06,57.23 30.06,56.4 v1(30.06,56.17)
  Bottom Layer w0.1: R97.2@30.06,55.45 v1(30.06,56.17) ; v1(30.06,56.17) 30.06,56.27 v1(30.06,56.17)
ETH_A_D1_N: J2.3 J16.L1 | length 32.5
  Top Layer w0.127: J2.3@64.338,45.658 64.376,45.697 64.385,45.697 64.426,45.737 64.426,45.986 64.718,46.278 65.839,46.278 66.259,45.858 66.259,45.577 66.4,45.437 v1(66.4,45.4)
  Bottom Layer w0.127: v1(66.4,45.4) 66.4,45.363 66.259,45.223 66.259,44.801 66.42,44.64 66.69,44.64 66.88,44.83 66.88,45.234 66.88,45.924 ccw(c66.753,45.924) 66.753,46.051 64.891,46.051 cw(c64.891,46.393) 64.891,46.735 66.769,46.735 ccw(c66.769,46.848) 66.769,46.962 64.891,46.962 cw(c64.891,47.304) 64.891,47.645 66.753,47.645 ccw(c66.753,47.772) 66.88,47.772 66.88,48.405 66.88,48.553 71.215,52.888 76.108,52.888 77.59,54.37 77.59,56.99 J16.L1@77.52,57.06
ETH_A_D1_P: J2.1 J16.L2 | length 32.5
  Top Layer w0.127: J2.1@64.738,45.662 64.704,45.697 64.695,45.697 64.654,45.737 64.654,45.891 64.813,46.05 65.744,46.05 66.031,45.764 66.031,45.577 65.89,45.437 v1(65.89,45.4)
  Bottom Layer w0.127: v1(65.89,45.4) 65.89,45.363 66.031,45.223 66.031,44.706 66.325,44.412 66.785,44.412 67.108,44.735 67.108,45.234 67.108,45.924 ccw(c66.753,45.924) 66.753,46.279 64.891,46.279 cw(c64.891,46.393) 64.891,46.506 66.769,46.506 ccw(c66.769,46.848) 66.769,47.19 64.891,47.19 cw(c64.891,47.304) 64.891,47.417 66.753,47.417 ccw(c66.753,47.772) 67.108,47.772 67.108,48.405 67.108,48.458 71.31,52.66 76.203,52.66 77.818,54.275 77.818,55.208 78.09,55.48 78.51,55.48 78.72,55.27 78.72,54.59 J16.L2@78.79,54.52
ETH_A_D2_N: J2.7 J16.L3 | length 33.1
  Top Layer w0.127: J2.7@63.538,45.658 63.576,45.697 63.576,45.704 63.61,45.737 63.61,46.314 64.376,47.08 67.704,47.08 68.38,46.404 68.38,45.593 68.5,45.474 v1(68.5,45.4)
  Bottom Layer w0.127: v1(68.5,45.4) 68.5,45.363 68.359,45.223 68.359,44.917 68.528,44.748 68.885,44.748 69.05,44.913 69.05,45.48 69.05,46.41 ccw(c68.923,46.41) 68.923,46.537 68.201,46.537 cw(c68.201,46.879) 68.201,47.221 68.991,47.221 ccw(c68.991,47.334) 68.991,47.448 68.201,47.448 cw(c68.201,47.789) 68.201,48.131 68.923,48.131 ccw(c68.923,48.258) 69.05,48.258 69.05,48.891 69.05,49.288 71.659,51.898 78.219,51.898 80.04,53.719 80.04,57.02 J16.L3@80.06,57.04
ETH_A_D2_P: J2.5 J16.L4 | length 33.1
  Top Layer w0.127: J2.5@63.938,45.662 63.903,45.697 63.903,45.704 63.87,45.737 63.87,46.206 64.484,46.82 67.596,46.82 68.12,46.296 68.12,45.593 67.99,45.464 v1(67.99,45.4)
  Bottom Layer w0.127: v1(67.99,45.4) 67.99,45.363 68.131,45.223 68.131,44.822 68.433,44.52 68.979,44.52 69.278,44.819 69.278,45.48 69.278,46.41 ccw(c68.923,46.41) 68.923,46.765 68.201,46.765 cw(c68.201,46.879) 68.201,46.992 68.991,46.992 ccw(c68.991,47.334) 68.991,47.676 68.201,47.676 cw(c68.201,47.789) 68.201,47.903 68.923,47.903 ccw(c68.923,48.258) 69.278,48.258 69.278,48.891 69.278,49.194 71.754,51.67 78.314,51.67 80.268,53.624 80.268,55.188 80.55,55.47 81.09,55.47 81.295,55.265 81.295,54.555 J16.L4@81.33,54.52
ETH_A_D3_N: J2.11 J16.L5 | length 33
  Top Layer w0.127: J2.11@62.738,45.658 62.776,45.697 62.785,45.697 62.826,45.737 62.826,46.644 64.039,47.858 69.699,47.858 70.374,47.183 70.374,46.888 70.51,46.752 v1(70.51,46.71)
  Bottom Layer w0.127: v1(70.51,46.71) 70.51,46.669 70.374,46.533 70.374,46.222 70.528,46.068 70.905,46.068 71.023,46.187 71.023,46.88 71.023,47.384 ccw(c70.896,47.384) 70.896,47.511 70.854,47.511 cw(c70.854,47.852) 70.854,48.194 71.03,48.194 ccw(c71.03,48.308) 71.03,48.421 70.854,48.421 cw(c70.854,48.763) 70.854,49.105 70.896,49.105 ccw(c70.896,49.232) 71.023,49.232 71.023,49.865 71.023,50.196 71.757,50.93 79.802,50.93 82.6,53.729 J16.L5@82.6,57.04
ETH_A_D3_P: J2.9 J16.L6 | length 33.1
  Top Layer w0.127: J2.9@63.138,45.662 63.104,45.697 63.095,45.697 63.054,45.737 63.054,46.55 64.134,47.63 69.604,47.63 70.146,47.088 70.146,46.897 70.01,46.761 v1(70.01,46.72)
  Bottom Layer w0.127: v1(70.01,46.72) 70.01,46.678 70.146,46.542 70.146,46.128 70.433,45.84 70.999,45.84 71.251,46.092 71.251,46.88 71.251,47.384 ccw(c70.896,47.384) 70.896,47.739 70.854,47.739 cw(c70.854,47.852) 70.854,47.966 71.03,47.966 ccw(c71.03,48.308) 71.03,48.65 70.854,48.65 cw(c70.854,48.763) 70.854,48.877 70.896,48.877 ccw(c70.896,49.232) 71.251,49.232 71.251,49.865 71.251,50.102 71.852,50.702 79.896,50.702 82.83,53.636 82.83,55.24 83.07,55.48 83.48,55.48 83.69,55.27 83.69,54.7 J16.L6@83.87,54.52
ETH_A_D4_N: J2.15 J16.L7 | length 32.9
  Top Layer w0.127: J2.15@61.938,45.658 61.976,45.697 61.985,45.697 62.026,45.737 62.026,46.914 63.709,48.598 71.764,48.598 72.384,47.978 72.384,47.698 72.52,47.562 v1(72.52,47.52)
  Bottom Layer w0.127: v1(72.52,47.52) 72.52,47.479 72.384,47.343 72.384,47.142 72.475,47.051 73.513,47.051 74.709,48.248 80.419,48.248 85.18,53.009 85.18,56.188 85.221,56.228 85.221,56.959 J16.L7@85.14,57.04
ETH_A_D4_P: J2.13 J16.L8 | length 33
  Top Layer w0.127: J2.13@62.338,45.662 62.303,45.697 62.295,45.697 62.254,45.737 62.254,46.82 63.804,48.37 71.67,48.37 72.156,47.884 72.156,47.698 72.02,47.562 v1(72.02,47.52)
  Bottom Layer w0.127: v1(72.02,47.52) 72.02,47.479 72.156,47.343 72.156,47.047 72.38,46.823 73.607,46.823 74.804,48.02 80.514,48.02 85.408,52.914 85.408,55.188 85.71,55.49 86.15,55.49 86.375,55.265 86.375,54.555 J16.L8@86.41,54.52
ETH_B_D1_N: J2.25 J16.R1 | length 23.5
  Top Layer w0.127: v1(57.3,51.45) 57.342,51.45 57.478,51.586 58.154,51.586 58.403,51.586 60.036,49.953 60.036,46.485 60.026,46.475 60.026,45.737 59.985,45.697 59.976,45.697 59.938,45.658 J2.25@59.938,45.129
  Bottom Layer w0.127: v1(57.3,51.45) 57.226,51.45 57.09,51.586 56.874,51.586 56.602,51.858 56.602,52.302 56.97,52.67 57.08,52.67 57.41,52.67 57.588,52.67 ccw(c57.588,52.797) 57.715,52.797 57.715,53.351 cw(c58.057,53.351) 58.398,53.351 58.398,52.512 ccw(c58.512,52.512) 58.625,52.512 58.625,53.351 cw(c58.967,53.351) 59.309,53.351 59.309,53.059 ccw(c59.436,53.059) 59.526,52.969 59.662,53.105 59.92,53.363 60.855,54.298 62.211,54.298 63.008,54.298 63.55,54.84 63.55,55.393 63.72,55.563 63.72,56.89 J16.R1@63.55,57.06
ETH_B_D1_P: J2.23 J16.R2 | length 23.5
  Top Layer w0.127: v1(57.3,51.95) 57.342,51.95 57.478,51.814 58.248,51.814 58.497,51.814 60.264,50.047 60.264,46.391 60.254,46.381 60.254,45.737 60.295,45.697 60.303,45.697 60.338,45.662 J2.23@60.338,45.129
  Bottom Layer w0.127: v1(57.3,51.95) 57.226,51.95 57.09,51.814 56.969,51.814 56.83,51.953 56.83,52.207 57.065,52.442 57.08,52.442 57.41,52.442 57.588,52.442 ccw(c57.588,52.797) 57.943,52.797 57.943,53.351 cw(c58.057,53.351) 58.17,53.351 58.17,52.512 ccw(c58.512,52.512) 58.854,52.512 58.854,53.351 cw(c58.967,53.351) 59.081,53.351 59.081,53.059 ccw(c59.436,53.059) 59.688,52.808 59.823,52.943 59.92,53.04 60.95,54.07 62.26,54.07 63.103,54.07 63.17,54.137 63.778,54.745 63.778,55.298 64.03,55.55 64.39,55.55 64.617,55.324 64.617,54.704 J16.R2@64.82,54.5
ETH_B_D2_N: J2.29 J16.R3 | length 23.4
  Top Layer w0.127: v1(57.3,49.7) 57.374,49.7 57.494,49.82 58.286,49.82 59.21,48.896 59.21,45.73 59.138,45.658 J2.29@59.138,45.129
  Bottom Layer w0.127: v1(57.3,49.7) 57.259,49.7 57.123,49.836 56.894,49.836 56.667,50.063 56.667,50.69 56.955,50.978 57.138,50.978 57.771,50.978 ccw(c57.771,51.105) 57.898,51.105 57.898,51.167 cw(c58.239,51.167) 58.581,51.167 58.581,50.355 ccw(c58.695,50.355) 58.808,50.355 58.808,50.623 cw(c59.164,50.623) 59.164,50.978 59.341,50.978 59.394,50.978 61.614,53.198 65.394,53.198 66.166,53.97 66.166,56.964 J16.R3@66.09,57.04
ETH_B_D2_P: J2.27 J16.R4 | length 23.4
  Top Layer w0.127: v1(57.3,50.2) 57.374,50.2 57.494,50.08 58.394,50.08 59.47,49.004 59.47,45.73 59.538,45.662 J2.27@59.538,45.129
  Bottom Layer w0.127: v1(57.3,50.2) 57.259,50.2 57.123,50.064 56.989,50.064 56.896,50.157 56.896,50.596 57.05,50.75 57.138,50.75 57.771,50.75 ccw(c57.771,51.105) 58.126,51.105 58.126,51.167 cw(c58.239,51.167) 58.353,51.167 58.353,50.355 ccw(c58.695,50.355) 59.037,50.355 59.037,50.623 cw(c59.164,50.623) 59.164,50.75 59.341,50.75 59.489,50.75 61.708,52.97 65.488,52.97 66.395,53.876 66.395,55.115 66.71,55.43 67.17,55.43 67.36,55.24 J16.R4@67.36,54.52
ETH_B_D3_N: J2.33 J16.R5 | length 23.3
  Top Layer w0.127: v1(57.3,47.94) 57.364,47.94 57.494,48.07 57.976,48.07 58.41,47.636 58.41,46.442 58.41,45.73 58.338,45.658 J2.33@58.338,45.129
  Bottom Layer w0.127: v1(57.3,47.94) 57.263,47.94 57.123,48.081 56.842,48.081 56.622,48.301 56.622,48.895 56.955,49.228 57.255,49.228 57.872,49.228 cw(c57.872,48.873) 58.227,48.873 58.227,48.752 ccw(c58.341,48.752) 58.454,48.752 58.454,48.873 cw(c58.809,48.873) 58.809,49.228 58.987,49.228 59.344,49.228 62.314,52.198 66.919,52.198 68.67,53.949 68.67,57 J16.R5@68.63,57.04
ETH_B_D3_P: J2.31 J16.R6 | length 23.4
  Top Layer w0.127: v1(57.3,48.45) 57.374,48.45 57.494,48.33 58.084,48.33 58.67,47.744 58.67,46.334 58.67,45.73 58.738,45.662 J2.31@58.738,45.129
  Bottom Layer w0.127: v1(57.3,48.45) 57.264,48.45 57.123,48.309 56.937,48.309 56.85,48.396 56.85,48.8 57.05,49 57.255,49 57.872,49 cw(c57.872,48.873) 57.999,48.873 57.999,48.752 ccw(c58.341,48.752) 58.682,48.752 58.682,48.873 cw(c58.809,48.873) 58.809,49 58.987,49 59.438,49 62.408,51.97 67.014,51.97 68.898,53.854 68.898,55.188 69.13,55.42 69.66,55.42 69.815,55.265 69.815,54.605 J16.R6@69.9,54.52
ETH_B_D4_N: J2.37 J16.R7 | length 23.4
  Top Layer w0.127: v1(57.2,46.15) 57.2,46.269 57.413,46.269 57.593,46.089 57.593,45.184 J2.37@57.57,45.161
  Bottom Layer w0.127: v1(57.2,46.15) 57.163,46.15 57.023,46.291 56.742,46.291 56.522,46.511 56.522,47.095 56.855,47.428 59.344,47.428 62.864,50.948 67.914,50.948 71.21,54.244 71.21,57 J16.R7@71.17,57.04
ETH_B_D4_P: J2.35 J16.R8 | length 23.4
  Top Layer w0.127: v1@57.2,46.65 57.2,46.53 57.521,46.53 57.854,46.197 57.854,45.214 57.908,45.159 J2.35@57.938,45.129
  Bottom Layer w0.127: v1@57.2,46.65 57.153,46.65 57.023,46.519 56.837,46.519 56.75,46.606 56.75,47 56.95,47.2 59.438,47.2 62.958,50.72 68.008,50.72 71.438,54.15 71.438,55.048 71.78,55.39 72.22,55.39 72.345,55.265 72.345,54.615 J16.R8@72.44,54.52
  other v1: 57.2,46.66
FRS_EN1: U29.C4 U30.1 | length 9.7
  Top Layer w0.1: v1(28.566,60.35) 28.59,60.35 U29.C4@28.59,58.82
  Int2 (Sign) w0.1: v1(28.566,60.35) 28.586,60.33 31.29,60.33 v1(32.84,58.78)
  Bottom Layer w0.1: U30.1@32.63,55.96 32.63,56.5 32.21,56.92 32.21,58.15 v1(32.84,58.78)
